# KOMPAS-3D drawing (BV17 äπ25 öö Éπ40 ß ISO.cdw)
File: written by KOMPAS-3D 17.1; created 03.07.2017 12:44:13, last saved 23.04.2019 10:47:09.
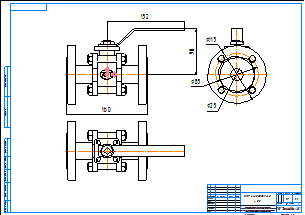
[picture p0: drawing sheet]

Sheet 1: A2, landscape

Title block, sheet 1: name: BV17 Ду25 ФФ Ру40 / с ISO; material: Внимание! Данный продукт является объектом авторского права ООО «Торговый Дом АДЛ». / Запрещается изменение, копирование, распространение / (в том числе путем копирования на другие сайты и ресурсы в Интернете) / или любое иное использование информации и объектов без предварительного / согласия правообладателя (ООО «Торговый Дом АДЛ»).; mass: 1,7; sheets: 1; organisation: ООО "Торговый дом АДЛ"; sheet format: A2; stored path: C:\Users\kka\KOMPAS_Work\!Trash\СС02 СС03 ФФ Смотровые стекла\СС01.cdw

Views: Спереди 1, Проекционный вид 2, Проекционный вид 3
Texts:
  Klimkovich
  ADL
Dimensions and other numbers on the sheet: 160; 152; 90; 85; 115; 25; 1:1; 1; 1,7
